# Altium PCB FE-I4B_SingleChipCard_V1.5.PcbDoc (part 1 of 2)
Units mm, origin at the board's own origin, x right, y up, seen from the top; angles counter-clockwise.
Board outline 100 x 100 mm, 5 copper layers (Top Layer, pad layer, GND, power, Bottom Layer); 136 components, 118 nets, 544 pads, 176 vias.
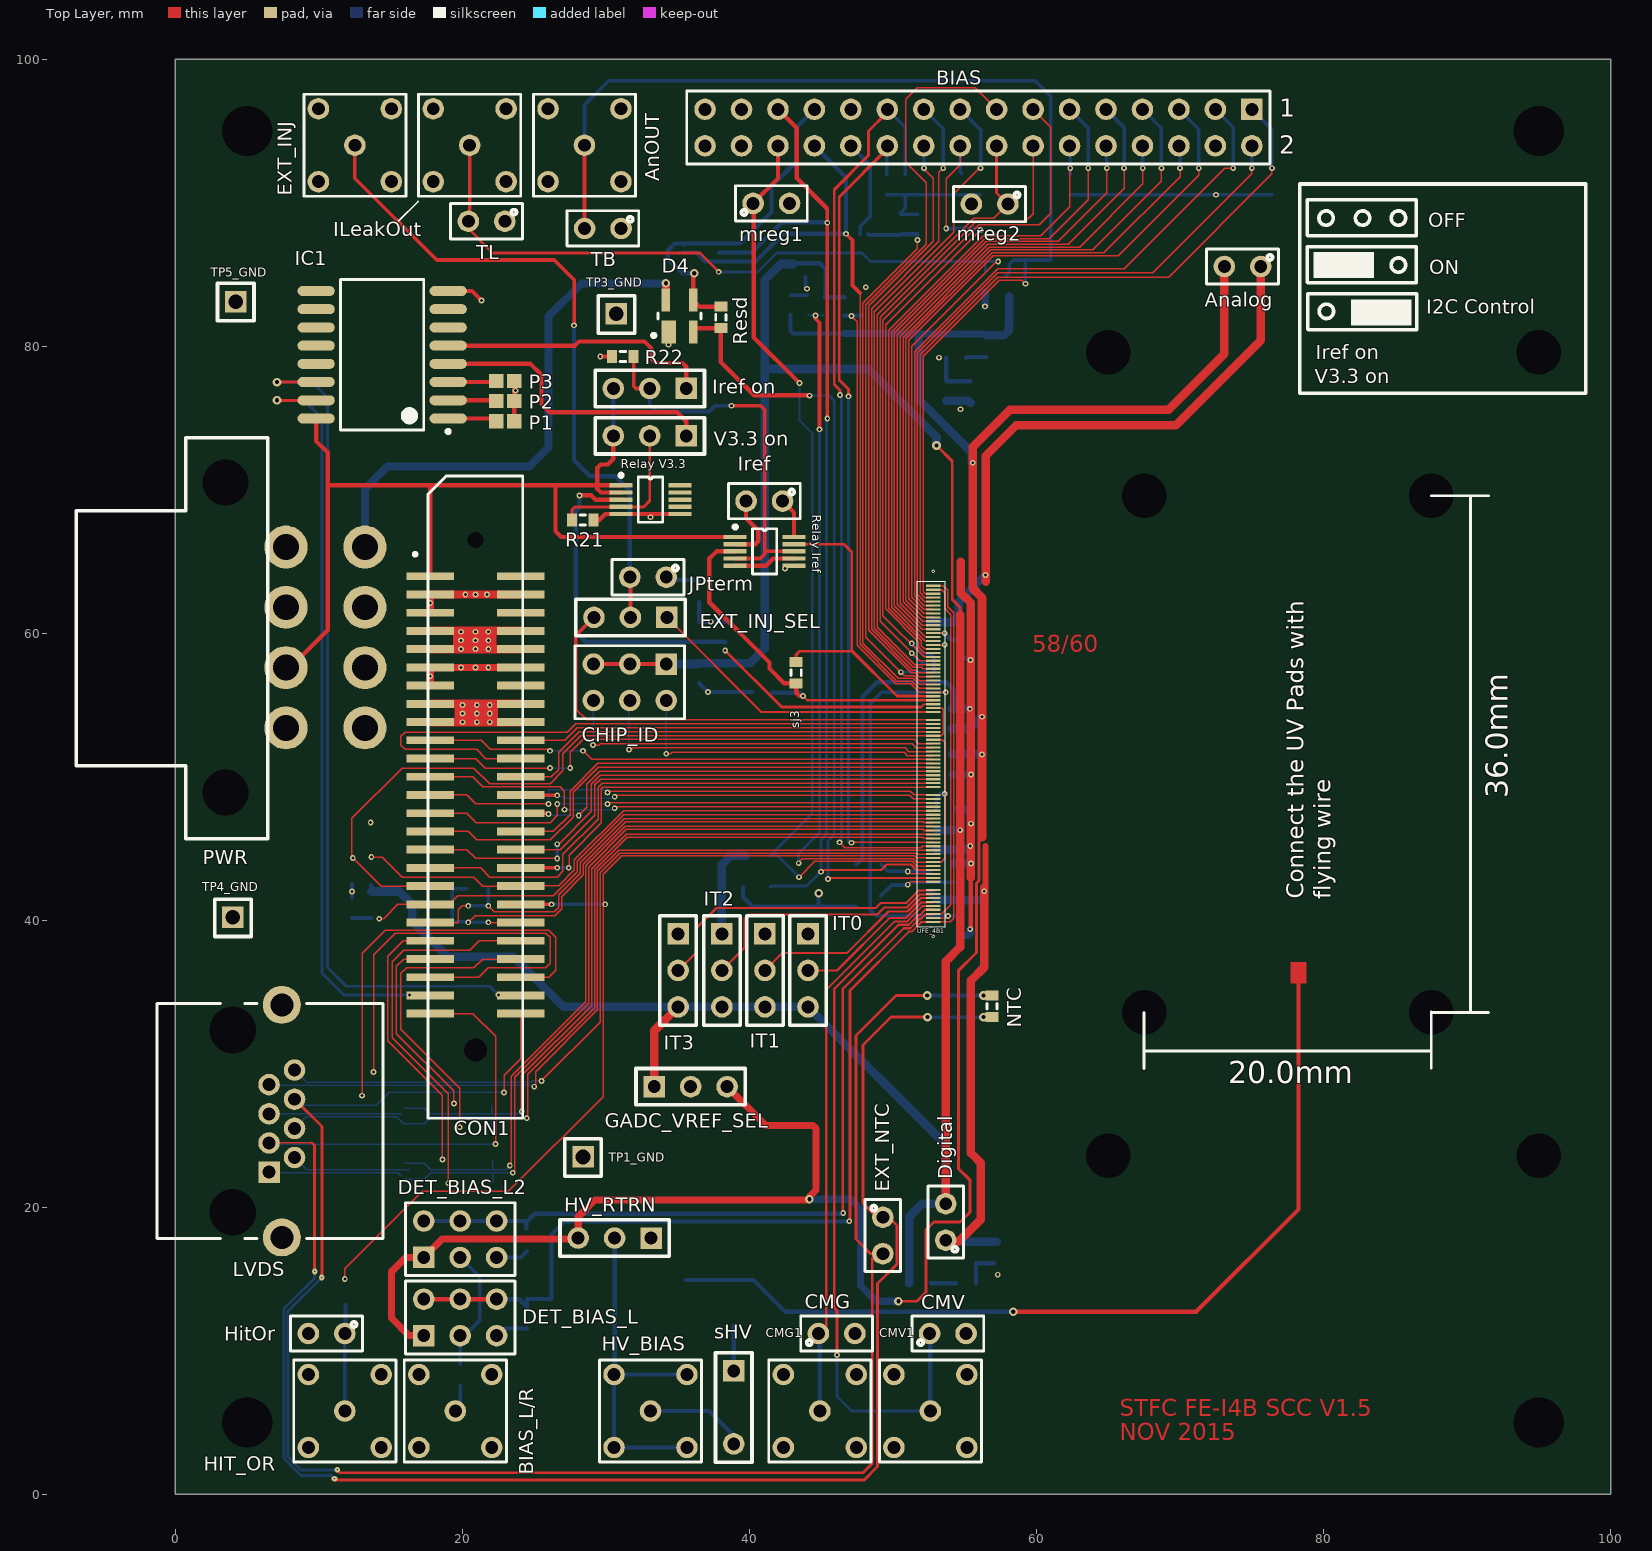
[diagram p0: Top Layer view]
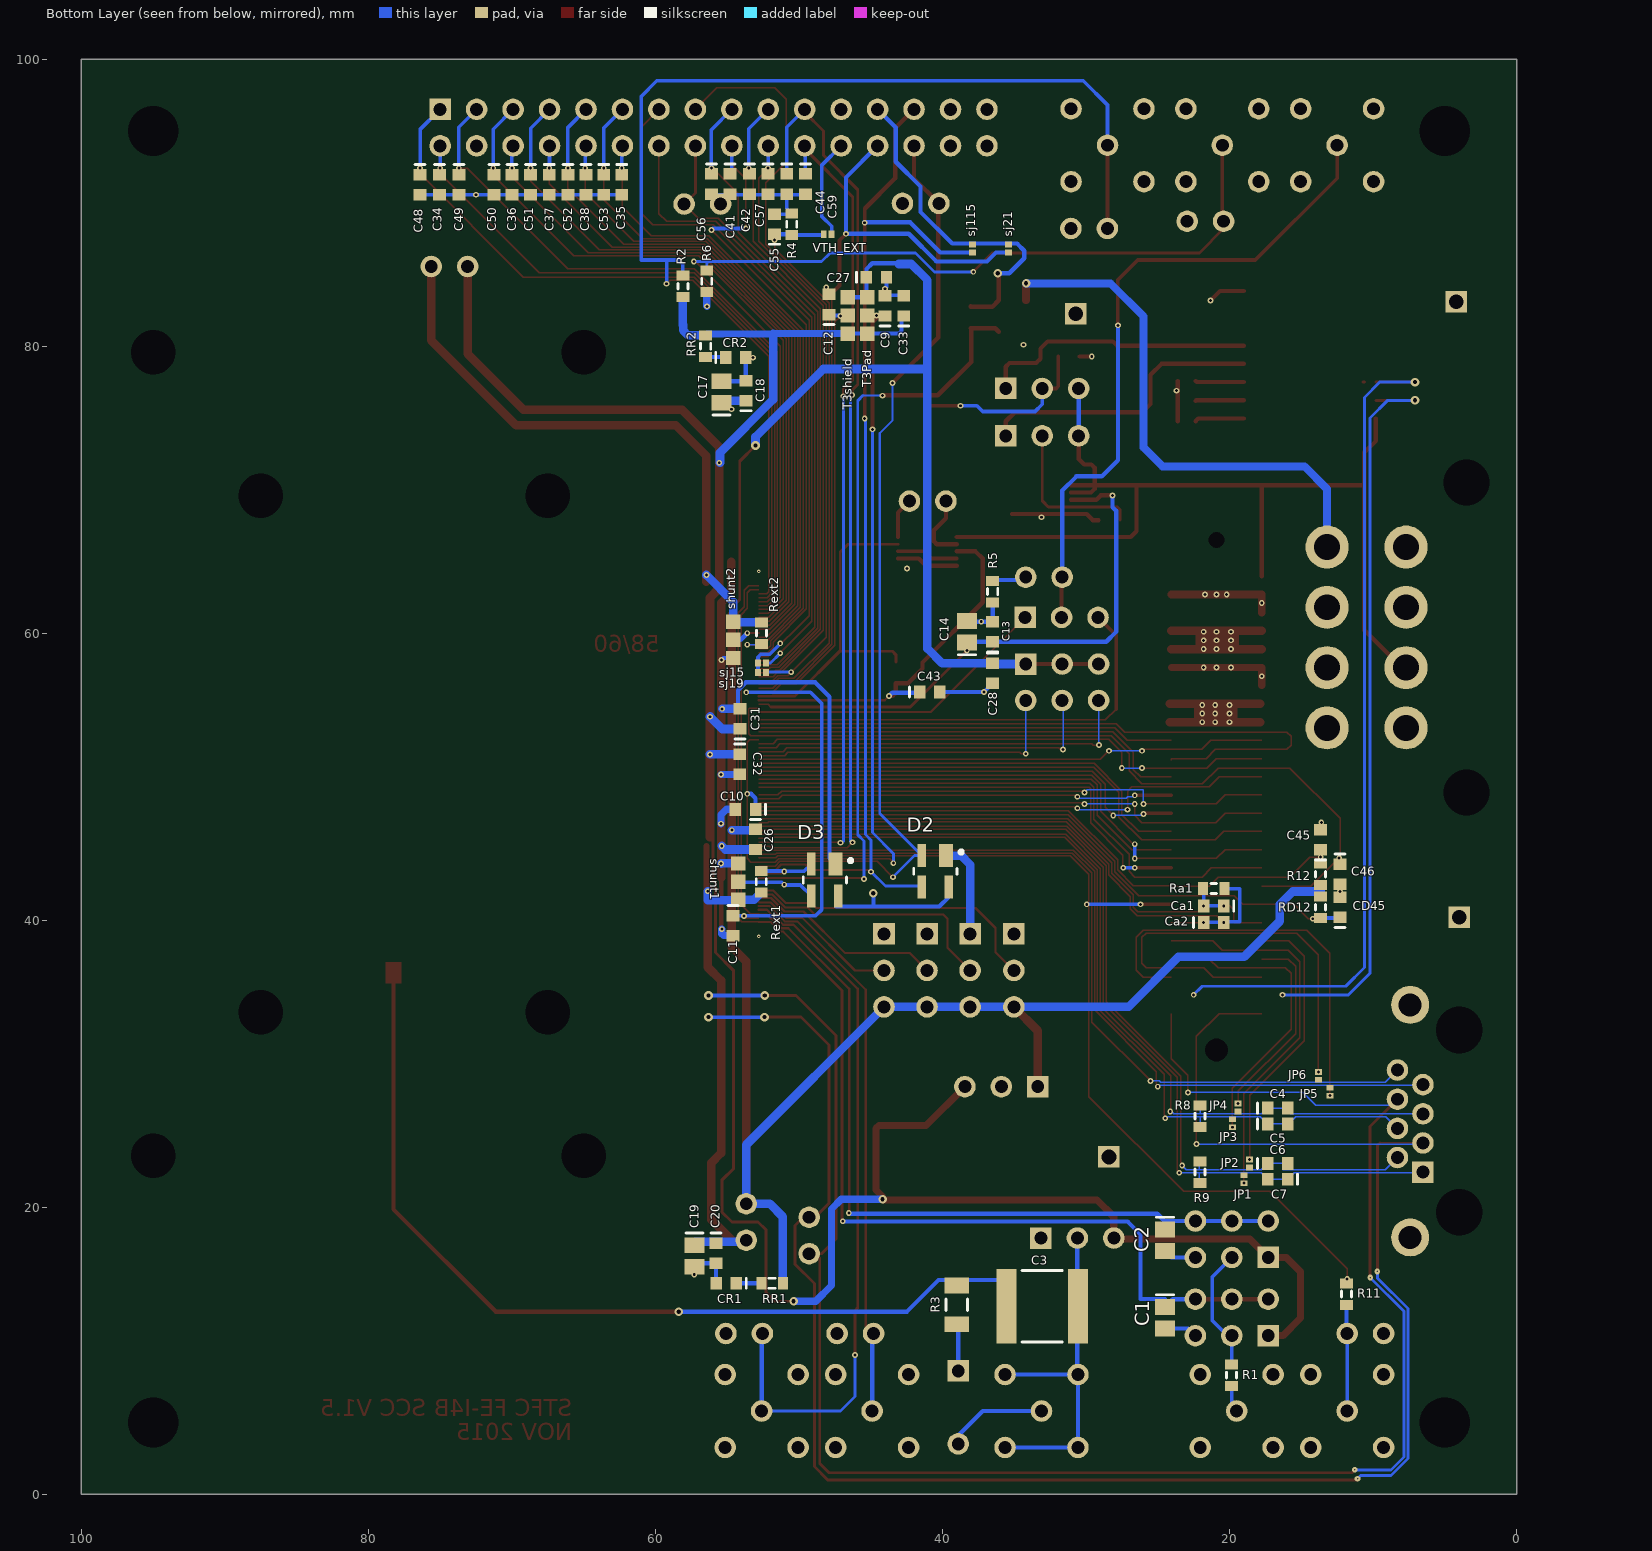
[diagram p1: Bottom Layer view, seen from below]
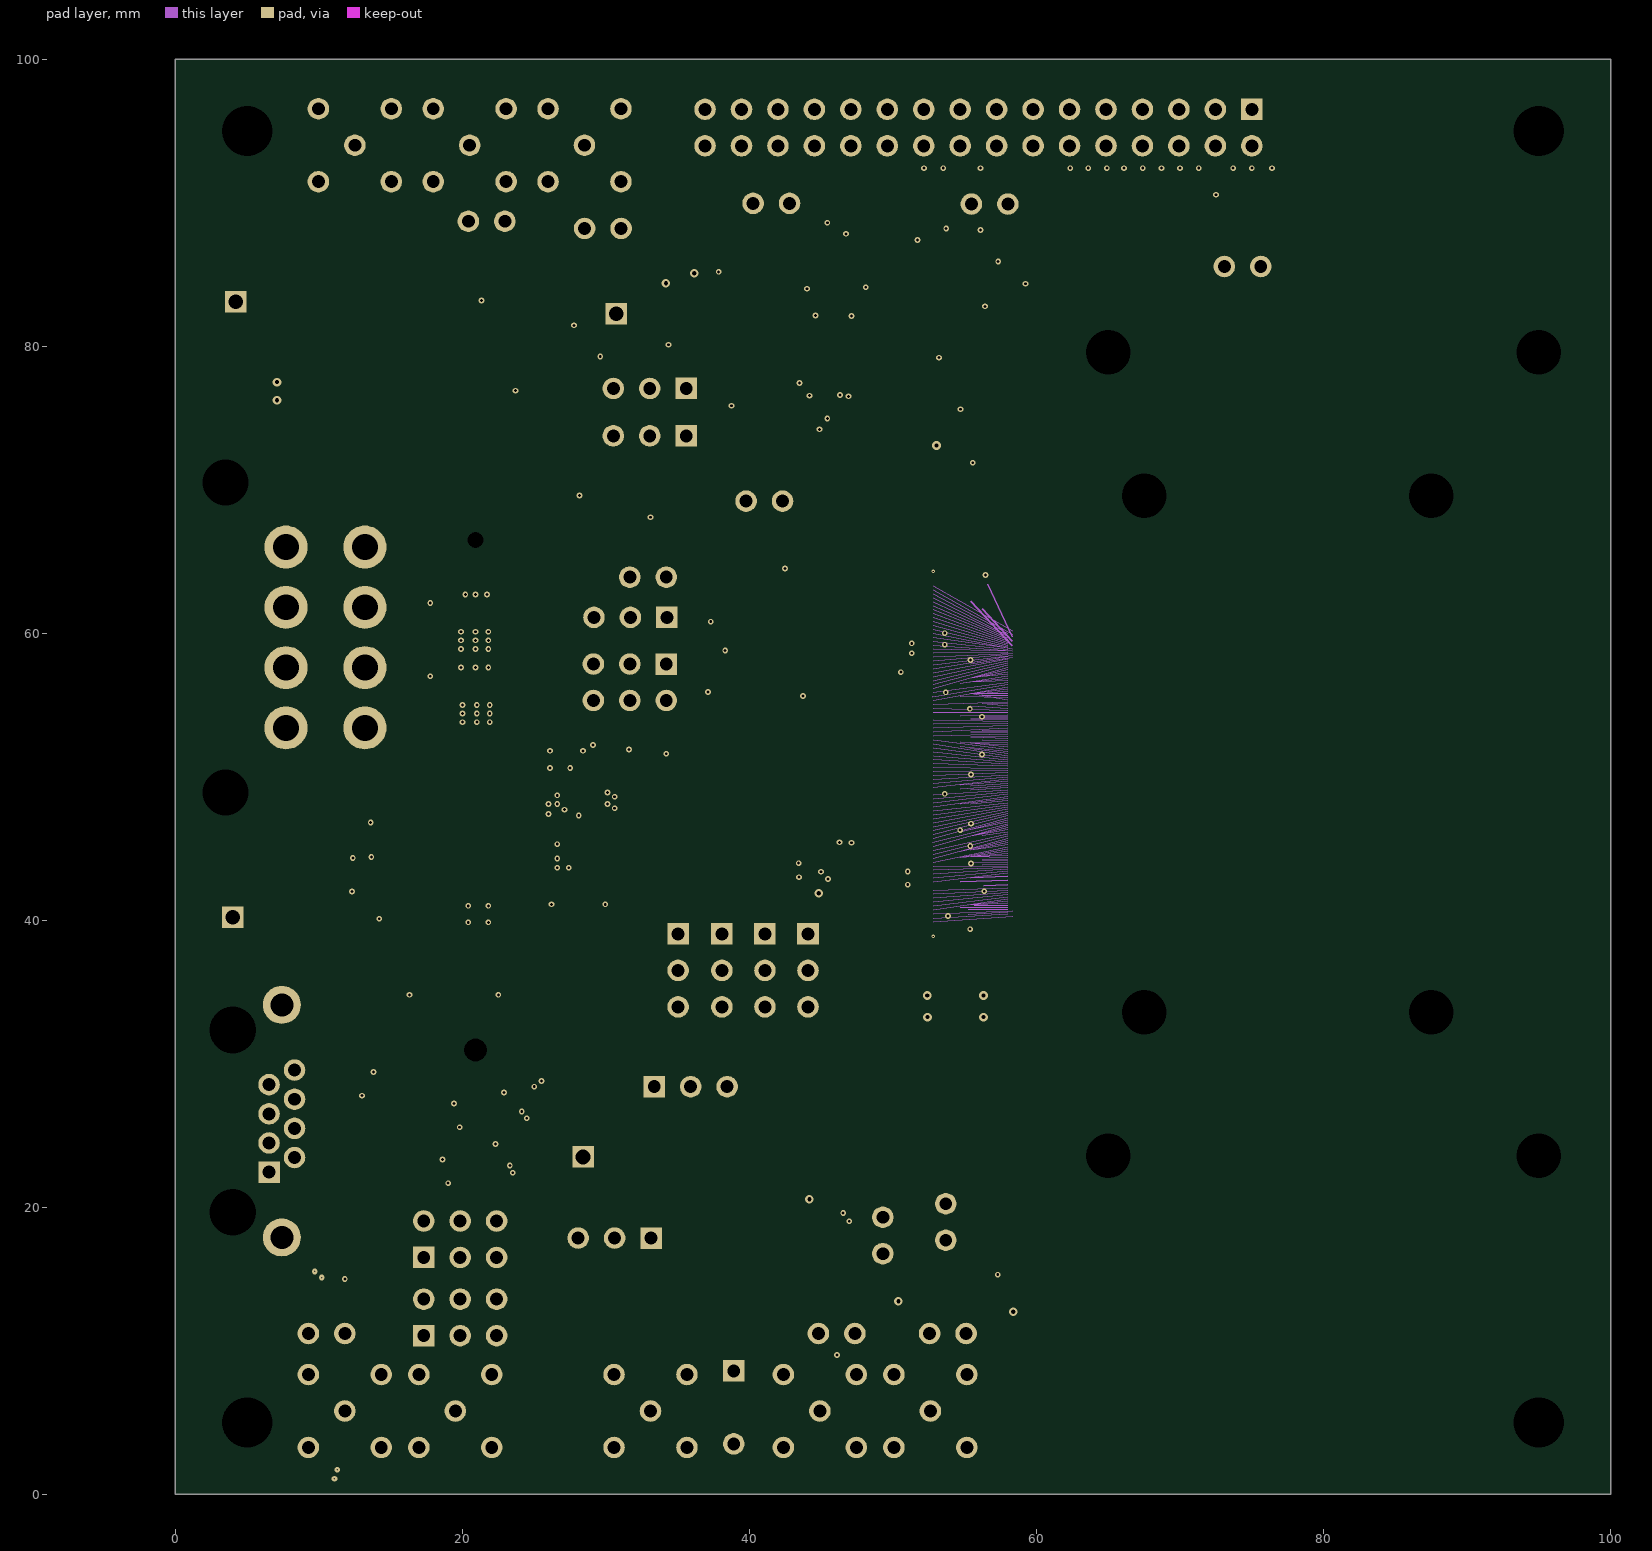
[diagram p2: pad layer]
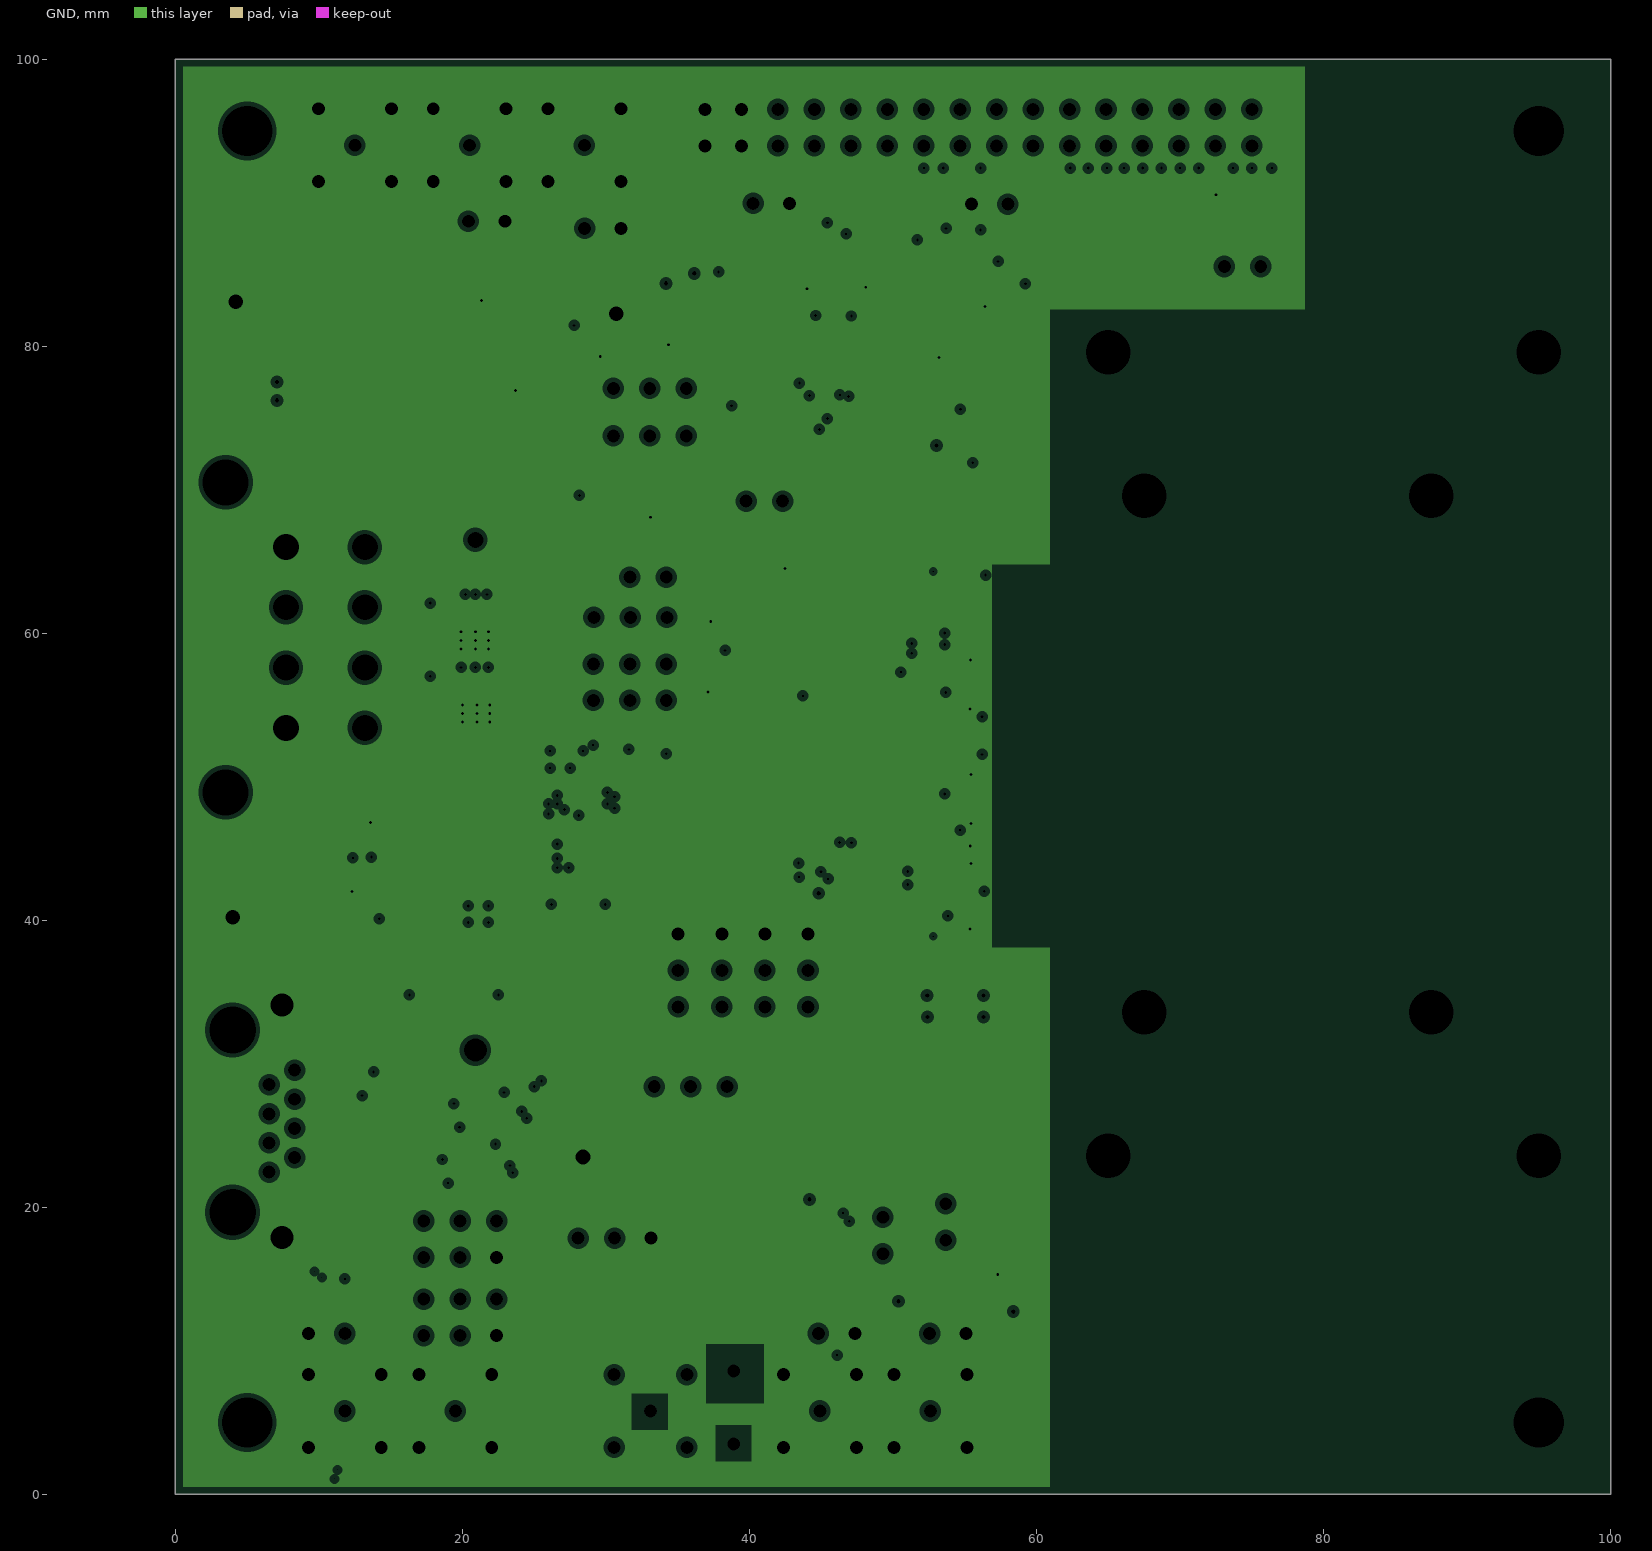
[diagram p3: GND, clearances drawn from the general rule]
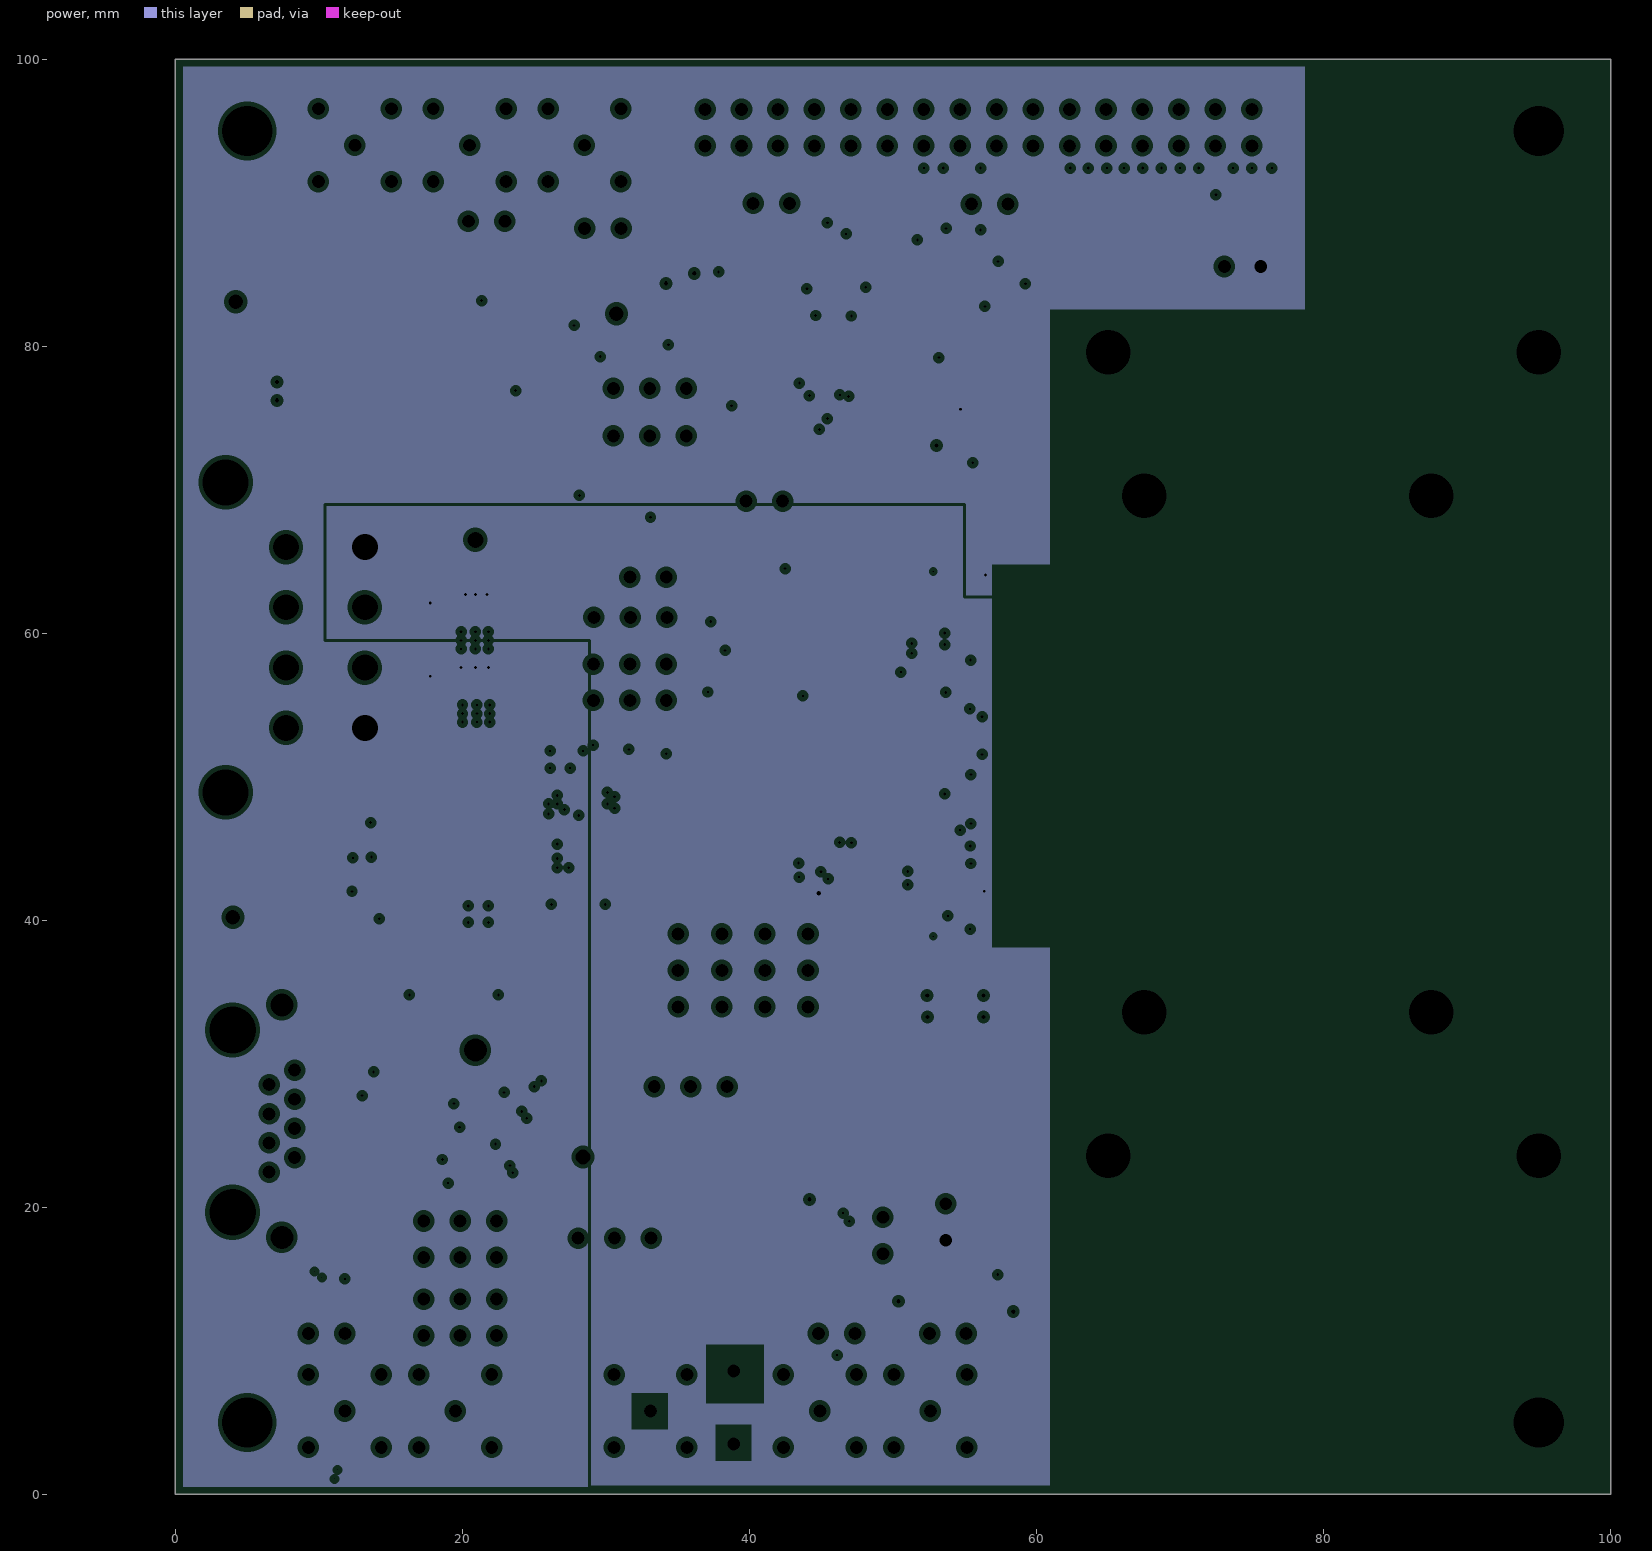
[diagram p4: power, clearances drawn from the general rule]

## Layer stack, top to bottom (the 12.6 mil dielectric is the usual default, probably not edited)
Top Solder: solder mask 0.0102, Solder Resist, Dk 3.5
Top Layer: signal copper 0.0356
Dielectric1: core 0.32, FR-4, Dk 4.8
pad layer: signal copper 0.0356
Dielectric2: prepreg 0.32, FR-4, Dk 4.8
GND: plane copper 0.0356, net GND
Dielectric3: core 0.32, FR-4, Dk 4.8
power: plane copper 0.0356, net (Multiple Nets)
Dielectric4: prepreg 0.32, FR-4, Dk 4.8
Bottom Layer: signal copper 0.0356
Bottom Solder: solder mask 0.0102, Solder Resist, Dk 3.5

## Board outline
0,0 0,100 100,100 100,0

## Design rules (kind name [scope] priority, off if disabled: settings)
Clearance "Clearance bot" [OnLayer('Bottom Layer')] p1: gap=0.09
Clearance "Clearance top" [OnLayer('Top Layer')] p2: gap=0.09
ComponentClearance [All] p1: gap=0.05 collisioncheckmode=3 verticalgap=0.254 showdistances=FALSE
FabricationTestPointUsage TestPointUsage [All] p1: valid=0 allowmultiple=FALSE
FabricationTestpoint Testpoint [All] p1: side=3 testpointundercomponent=TRUE minsize=1.016 maxsize=2.54 preferedsize=1.524 minholesize=0 maxholesize=1.016 preferedholesize=0.813 testpointgrid=0.025 allowsidetop=TRUE allowsidebottom=TRUE usegrid=TRUE gridtolerance=0
HoleSize [All] p1: absolutevalues=TRUE maxlimit=5 minlimit=0 maxpercent=80.000 minpercent=20.000
PlaneClearance [All] p1: clearance=0.3
PlaneConnect PlaneConnect_Thermal [(InComponent('U1') AND InNet('GNDA'))] p1: planeconnectstyle=Direct reliefexpansion=0.508 reliefentries=4 reliefconductorwidth=0.254 reliefairgap=0.254
PlaneConnect [NOT(InComponent('U1') AND InNet('GNDA'))] p2: planeconnectstyle=Direct reliefexpansion=0.508 reliefentries=4 reliefconductorwidth=0.254 reliefairgap=0.254
PolygonConnect PolygonConnect_Thermal [InNet('GNDA')] p1: connectstyle=Direct reliefconductorwidth=0.254 reliefentries=4 polygonreliefangle="90 Angle" airgapwidth=0.254
PolygonConnect [NOT(InComponent('U1') AND InNet('GNDA'))] p2: connectstyle=Relief reliefconductorwidth=0.254 reliefentries=4 polygonreliefangle="90 Angle" airgapwidth=0.254
RoutingLayers [OnLayer('pad layer')] p1: top layer_v5=TRUE mid layer 1_v5=TRUE bottom layer_v5=TRUE
RoutingVias [All] p1: holewidth=0.2 width=0.4 viastyle="Through Hole" minholewidth=0 minwidth=0.4 maxholewidth=4 maxwidth=5
ShortCircuit "ShortCircuit pad" [OnLayer('pad layer') vs OnLayer('pad layer')] p1: allowed=TRUE
ShortCircuit "ShortCircuit bot" [OnLayer('Bottom Layer')] p2: allowed=FALSE
ShortCircuit "ShortCircuit top" [OnLayer('Top Layer')] p3: allowed=FALSE
SilkToSolderMaskClearance SilkscreenOverComponentPads [IsPad] p1: minsilkscreentomaskgap=0.254 clearancetoexposedcopper=TRUE
SolderMaskExpansion [All] p1: expansion=0.102
UnConnectedPin [All] p1 off:
UnRoutedNet [NOT (OnLayer('padLayer'))] p1:
Width "Width pad" [All] p1: maxlimit=3 minlimit=0.01 preferedwidth=0.254 minimp=50.000000 maximp=50.000000 favimp=50.000000
Width "Width bot" [OnLayer('Bottom Layer')] p2: maxlimit=5 minlimit=0.125 preferedwidth=0.2
Width "Width top" [All] p3: maxlimit=4 minlimit=0.01 preferedwidth=0.25 minimp=50.000000 maximp=50.000000 favimp=50.000000
19 further rules are at their usual default settings.

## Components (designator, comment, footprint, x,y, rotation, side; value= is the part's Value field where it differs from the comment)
Analog "Jumper, 1x2" "CON 1x2 std" 75.625,85.55 r180 top
AnOUT "LEMO Connector" LEMO 28.5,94 r0 top
BIAS "Header 16X2" HDR2X16 75,96.5 r180 top locked
BIAS_L/R "LEMO Connector" LEMO 19.5,5.8 r0 top
C1 "X7R" C0805_imp_L 24.5,12.3 r270 bottom
C2 "X7R" C0805_imp_L 24.5,17.7 r270 bottom
C3 "X7R" C5750_met_L 33.05,13.1 r180 bottom
C4 "X7R" C0603_imp_L 16.65,26.9 r180 bottom
C5 "X7R" C0603_imp_L 16.65,25.8 r180 bottom
C6 "X7R" C0603_imp_L 16.65,23.05 r180 bottom
C7 "X7R" C0603_imp_L 16.65,21.95 r0 bottom
C9 "X7R" C0603_imp_L 44,82.8 r90 bottom
C10 "X7R" C0603_imp_L 53.725,47.725 r0 bottom
C11 "X7R" C0603_imp_L 54.6,39.625 r270 bottom
C12 "X7R" C0603_imp_L 47.9,82.9 r90 bottom
C13 "X7R" C0603_imp_L 36.5,60.1 r90 bottom
C14 "X7R" C0805_imp_L 38.3,60.1 r90 bottom
C17 "X7R" C0805_imp_L 55.4,76.8 r90 bottom
C18 "X7R" C0603_imp_L 53.7,76.9 r90 bottom
C19 "X7R" C0805_imp_L 57.275,16.6 r270 bottom
C20 "X7R" C0603_imp_L 55.775,16.8 r270 bottom
C26 "X7R" C0603_imp_L 53.025,45.625 r270 bottom
C27 "X7R" C0603_imp_L 44.6,84.8 r180 bottom
C28 "X7R" C0603_imp_L 36.5,57.2 r270 bottom
C31 "X7R" C0603_imp_L 54.1,54.025 r90 bottom
C32 "X7R" C0603_imp_L 54.125,50.875 r270 bottom
C33 "X7R" C0603_imp_L 42.7,82.8 r90 bottom
C34 "X7R" C0603_imp_L 75.05,91.25 r270 bottom
C35 "X7R" C0603_imp_L 62.35,91.25 r270 bottom
C36 "X7R" C0603_imp_L 70,91.25 r270 bottom
C37 "X7R" C0603_imp_L 67.4,91.25 r270 bottom
C38 "X7R" C0603_imp_L 64.85,91.25 r270 bottom
C41 "X7R" C0603_imp_L 54.8,91.3 r270 bottom
C42 "X7R" C0603_imp_L 53.45,91.3 r270 bottom
C43 "X7R" C0603_imp_L 40.9,55.9 r180 bottom
C44 "X7R" C0603_imp_L 50.85,91.3 r270 bottom
C45 "X7R" C0603_imp_L 13.65,45.6 r90 bottom
C46 "X7R" C0603_imp_L 12.3,43.2 r270 bottom
C48 "X7R" C0603_imp_L 76.4,91.25 r270 bottom
C49 "X7R" C0603_imp_L 73.7,91.25 r270 bottom
C50 "X7R" C0603_imp_L 71.25,91.25 r270 bottom
C51 "X7R" C0603_imp_L 68.7,91.25 r270 bottom
C52 "X7R" C0603_imp_L 66.1,91.25 r270 bottom
C53 "X7R" C0603_imp_L 63.6,91.25 r270 bottom
C55 "X7R" C0603_imp_L 51.7,88.5 r90 bottom
C56 "X7R" C0603_imp_L 56.1,91.3 r270 bottom
C57 "X7R" C0603_imp_L 52.15,91.3 r270 bottom
C59 "X7R" C0603_imp_L 49.55,91.3 r270 bottom
Ca1 "X7R" C0603_imp_L 21.1,41 r0 bottom
Ca2 "X7R" C0603_imp_L 21.1,39.85 r180 bottom
CD45 "X7R" C0603_imp_L 12.3,40.9 r90 bottom
CHIP_ID "Header 3X2" HDR2X3 34.2,57.85 r180 top
CMG "LEMO Connector" LEMO 44.9,5.8 r0 top
CMG1 "Jumper, 1x2" "CON 1x2 std" 44.8,11.2 r0 top
CMV "LEMO Connector" LEMO 52.6,5.8 r0 top
CMV1 "Jumper, 1x2" "CON 1x2 std" 52.55,11.2 r0 top
CON1 "KEL 8930E" "Kel_Connector 2x25; SMT" 17.6,64 r270 top locked
CR1 "X7R" C0603_imp_L 55.075,14.7 r0 bottom
CR2 "X7R" C0603_imp_L 54.4,79.2 r180 bottom
D2 "Molex 2X2" SOT143M 40.5,43.4 r270 bottom
D3 "Molex 2X2" SOT143M 48.2,42.8 r270 bottom
D4 "Molex 2X2" SOT143M 35.125,82.1 r90 top
DET_BIAS_L "Header 3X2" HDR2X3 17.3,11.05 r0 top
DET_BIAS_L2 "Header 3X2" HDR2X3 17.3,16.5 r0 top
Digital "Jumper, 1x2" "CON 1x2 std" 53.675,17.7 r90 top
EXT_INJ "LEMO Connector" LEMO 12.5,94 r0 top
EXT_INJ_SEL "Selector Jumper" "HDR 1x3" 31.7,61.1 r180 top
EXT_NTC "Jumper, 1x2" "CON 1x2 std" 49.288,19.3 r270 top
GADC_VREF_SEL "Selector Jumper" "HDR 1x3" 35.9,28.4 r0 top
HIT_OR "LEMO Connector" LEMO 11.8,5.8 r0 top
HitOr "Jumper, 1x2" "CON 1x2 std" 11.8,11.2 r180 top
HV_BIAS "LEMO Connector" LEMO 33.1,5.8 r0 top
HV_RTRN "Selector Jumper" "HDR 1x3" 30.6,17.85 r180 top
IC1 "i²C I/O" DW016_M 14.4,79.4 r180 top
ILeakOut "LEMO Connector" LEMO 20.5,94 r0 top
Iref "Jumper, 1x2" "CON 1x2 std" 42.3,69.2 r180 top
"Iref on" "Selector Jumper" "HDR 1x3" 33.05,77.05 r180 top
IT0 "Selector Jumper" "HDR 1x3" 44.075,36.5 r270 top
IT1 "Selector Jumper" "HDR 1x3" 41.075,36.5 r270 top
IT2 "Selector Jumper" "HDR 1x3" 38.075,36.5 r270 top
IT3 "Selector Jumper" "HDR 1x3" 35.025,36.5 r270 top
JP1 "Jumper, 1x2" "Lötjumper 1x2 - small" 19,21.95 r270 bottom
JP2 "Jumper, 1x2" "Lötjumper 1x2 - small" 18.6,23.05 r90 bottom
JP3 "Jumper, 1x2" "Lötjumper 1x2 - small" 19.8,25.85 r270 bottom
JP4 "Jumper, 1x2" "Lötjumper 1x2 - small" 19.4,26.95 r90 bottom
JP5 "Jumper, 1x2" "Lötjumper 1x2 - small" 13,28.05 r270 bottom
JP6 "Jumper, 1x2" "Lötjumper 1x2 - small" 13.8,29.15 r90 bottom
JPterm "Jumper, 1x2" "CON 1x2 std" 34.2,63.9 r180 top
LVDS "-" 44620-0002 -1.3,26 r270 top locked
mreg1 "Jumper, 1x2" "CON 1x2 std" 40.25,89.95 r0 top
mreg2 "Jumper, 1x2" "CON 1x2 std" 58,89.9 r180 top
NTC "R?" R0603_imp_L 56.9,34 r270 top
P1 "Jumper, Solderbridge 1x2" "Lötjumper 1x2" 22.986,74.773 r180 top
P2 "Jumper, Solderbridge 1x2" "Lötjumper 1x2" 22.986,76.173 r180 top
P3 "Jumper, Solderbridge 1x2" "Lötjumper 1x2" 22.986,77.573 r180 top
PWR "-" "MOLEX SD-5569" 7.7,66 r270 top locked
R1 "R?" R0603_imp_L 19.85,8.3 r90 bottom
R2 "R?" R0603_imp_L 58.075,84.175 r270 bottom
R3 "R?" R1206_imp_L 39,13.2 r90 bottom
R4 "R?" R0603_imp_L 50.5,88.5 r90 bottom
R5 "R?" R0603_imp_L 36.5,62.9 r90 bottom
R6 "R?" R0603_imp_L 56.425,84.525 r270 bottom
R8 "R?" R0603_imp_L 22.05,26.35 r90 bottom
R9 "R?" R0603_imp_L 22.05,22.45 r90 bottom
R11 "R?" R0603_imp_L 11.85,13.95 r90 bottom
R12 "R?" R0603_imp_L 13.65,43.2 r270 bottom
R21 "R?" R0603_imp_L 28.375,67.875 r180 top
R22 "R?" R0603_imp_L 31.175,79.275 r0 top
Ra1 "R?" R0603_imp_L 21.1,42.2 r0 bottom
RD12 "R?" R0603_imp_L 13.65,40.9 r90 bottom
"Relay Iref" "relay 4684EUB" UMAX10 41.05,65.7 r270 top
"Relay V3.3" "relay 4684EUB" UMAX10 33.1,69.3 r270 top
Resd "R?" R0603_imp_L 38,82 r90 top
Rext1 "R?" R0603_imp_L 52.625,42.675 r90 bottom
Rext2 "R?" R0603_imp_L 52.6,60 r270 bottom
RR1 "R?" R0603_imp_L 51.875,14.7 r180 bottom
RR2 "R?" R0603_imp_L 56.5,80 r90 bottom
shunt1 "Jumper, Solderbridge 1x3" solderjumper3 54.225,42.05 r90 bottom
shunt2 "Jumper, Solderbridge 1x3" solderjumper3 54.575,60.175 r270 bottom
sHV "Wire Bridge" "HDR 1;3" 38.9,6.05 r270 top
sj3 "R?" R0603_imp_L 43.25,57.25 r270 top
sj15 "Jumper, Solderbridge 1x2" "Lötjumper 1x2 - small" 52.578,57.912 r180 bottom
sj19 "Jumper, Solderbridge 1x2" "Lötjumper 1x2 - small" 52.578,57.25 r180 bottom
sj21 "Jumper, Solderbridge 1x2" "Lötjumper 1x2 - small" 35.4,86.8 r270 bottom
sj115 "Jumper, Solderbridge 1x2" "Lötjumper 1x2 - small" 37.9,86.8 r270 bottom
T3Pad "Jumper, Solderbridge 1x3" solderjumper3 45.25,81.5 r90 bottom
T3shield "Jumper, Solderbridge 1x3" solderjumper3 46.6,81.5 r90 bottom
TB "Jumper, 1x2" "CON 1x2 std" 31.05,88.2 r180 top
TL "Jumper, 1x2" "CON 1x2 std" 22.95,88.7 r180 top
TP1_GND "Test-Point" TEST_POINT 28.4,23.5 r270 top
TP3_GND "Test-Point" TEST_POINT 30.725,82.25 r270 top
TP4_GND "Test-Point" TEST_POINT 4,40.2 r270 top
TP5_GND "Test-Point" TEST_POINT 4.2,83.1 r270 top
UFE_4B1 "FE-I4B" "FE-I4B_PCB design" 52.8,63.3 r270 top
"V3.3 on" "Selector Jumper" "HDR 1x3" 33.05,73.75 r180 top
VTH_EXT "Jumper, Solderbridge 1x2" "Lötjumper 1x2 - small" 48,87.8 r180 bottom

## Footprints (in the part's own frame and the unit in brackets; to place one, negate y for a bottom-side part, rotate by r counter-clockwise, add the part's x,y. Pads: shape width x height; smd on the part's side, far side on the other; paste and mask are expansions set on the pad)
44620-0002 [mm]
  rect 1.5x1.5 hole 0.9: 1(3.556,7.82)
  round 1.5 hole 0.9: 2(2.54,9.598) 3(1.524,7.82) 4(0.508,9.598) 5(-0.508,7.82) 6(-1.524,9.598) 7(-2.54,7.82) 8(-3.556,9.598)
  round 2.65 hole 1.6: MH1(-8.103,8.709) MH2(8.103,8.709)
  round 2.95 hole 3.25 unplated: MH3(-6.35,5.28) MH4(6.35,5.28)
  silkscreen extent -8.19,0 8.19,15.75
C0603_imp_L [mm]
  rect 0.8x0.9 smd: 1(-0.7,0) 2(0.7,0)
  silkscreen extent -1.4,-0.35 -1.4,0.35, body extent -0.87,-0.48 0.87,0.48, height 0.85
C0805_imp_L [mm]
  rect 1.1x1.4 smd: 1(-0.75,0) 2(0.75,0)
  silkscreen extent -1.6,-0.6 -1.6,0.6, body extent -1.1,-0.72 1.1,0.72, height 1.1
C5750_met_L [mm]
  rect 1.4x5.2 smd: 1(-2.5,0) 2(2.5,0)
  silkscreen extent -1.4,-2.5 1.4,2.5, body extent -2.95,-2.63 2.95,2.63, height 1.35
"CON 1x2 std" [mm]
  round 1.5 hole 0.9: 1(0,0) 2(2.54,0)
  silkscreen extent -1.23,-1.23 3.78,1.23
DW016_M [mm] "16-Pin Plastic Small Outline Integrated Circuit 1.27 mm Pitch, IPC Low Density"
  oval 2.6x0.7 smd: 1(-4.6,4.445) 2(-4.6,3.175) 3(-4.6,1.905) 4(-4.6,0.635) 5(-4.6,-0.635) 6(-4.6,-1.905) 7(-4.6,-3.175) 8(-4.6,-4.445) 9(4.6,-4.445) 10(4.6,-3.175) 11(4.6,-1.905) 12(4.6,-0.635) 13(4.6,0.635) 14(4.6,1.905) 15(4.6,3.175) 16(4.6,4.445)
  silkscreen extent -4.72,-5.25 2.9,5.47, body extent -3.75,-5.25 3.75,5.25, height 2.65
"FE-I4B_PCB design" [mm] "bondpads FE-I4 on chip"
  rect 0.15x1 smd paste-1 mask+0: 1(0.55,0) 1b(0,0) 2(0.825,0) 2b(0.275,0) 3(1.1,0) 4(1.375,0) 5(1.65,0) 6(1.925,0) 6b(3.3,0) 7(2.2,0) 7b(4.125,0) 8(2.475,0) 8b(4.95,0) 9(2.75,0) 9b(5.5,0) 10(3.025,0) 11(3.575,0) 11b(22.875,0) 12(3.85,0) 12b(23.425,0) 13(4.4,0) 14(4.675,0) 15(5.225,0) 16(5.775,0) 17(6.05,0) 18(6.325,0) 19(6.6,0) 20(6.875,0) 21(7.15,0) 28(7.425,0) 29(7.7,0) 30(7.975,0) 37(8.25,0) 41(8.525,0) 42(8.8,0) 46(9.35,0) 47(9.625,0) 48(9.9,0) 49(10.175,0) 52(10.45,0) 59(10.725,0) 62(11,0) 63(11.275,0) 64(11.55,0) 65(11.825,0) 66(12.1,0) 67(12.375,0) 68(12.65,0) 69(12.925,0) 70(13.2,0) 71(13.475,0) 72(13.75,0) 73(14.025,0) 78(14.575,0) 79(14.85,0) 80(15.125,0) 81(15.4,0) 84(15.675,0) 85(15.95,0) 86(16.225,0) 87(16.5,0) 88(16.775,0) 89(17.05,0) 90(17.325,0) 91(17.6,0) 94(17.875,0) 95(18.15,0) 99(18.425,0) 100(18.7,0) 101(18.975,0) 105(19.25,0) 114(19.525,0) 115(19.8,0) 116(20.075,0) 117(20.35,0) 118(20.625,0) 122(21.2,0) 123(21.475,0) 124(21.75,0) 125(22.025,0) 126(22.3,0) 127(22.575,0) 134(23.15,0)
  silkscreen extent -0.3,-1.1 23.75,0.85
HDR2X3 [mm] "Connector; Header; 3x2 Position"
  rect 1.5x1.5 hole 0.9: 1(0,0)
  round 1.5 hole 0.9: 2(0,2.54) 3(2.54,0) 4(2.54,2.54) 5(5.08,0) 6(5.08,2.54)
  silkscreen extent -1.27,-1.27 6.35,3.81
HDR2X16 [mm] "Connector; Header; 16x2 Position"
  rect 1.5x1.5 hole 0.9: 1(0,0)
  round 1.5 hole 0.9: 2(0,2.54) 3(2.54,0) 4(2.54,2.54) 5(5.08,0) 6(5.08,2.54) 7(7.62,0) 8(7.62,2.54) 9(10.16,0) 10(10.16,2.54) 11(12.7,0) 12(12.7,2.54) 13(15.24,0) 14(15.24,2.54) 15(17.78,0) 16(17.78,2.54) 17(20.32,0) 18(20.32,2.54) 19(22.86,0) 20(22.86,2.54) 21(25.4,0) 22(25.4,2.54) 23(27.94,0) 24(27.94,2.54) 25(30.48,0) 26(30.48,2.54) 27(33.02,0) 28(33.02,2.54) 29(35.56,0) 30(35.56,2.54) 31(38.1,0) 32(38.1,2.54)
  silkscreen extent -1.27,-1.27 39.37,3.81
"HDR 1;3" [mm] "Steckjumper 2 pins"
  rect 1.5x1.5 hole 0.9: 1(-2.54,0)
  round 1.5 hole 0.9: 3(2.54,0)
  silkscreen extent -3.81,-1.27 3.81,1.27
"HDR 1x3" [mm]
  rect 1.5x1.5 hole 0.9: 1(-2.54,0)
  round 1.5 hole 0.9: 2(0,0) 3(2.54,0)
  silkscreen extent -3.81,-1.27 3.81,1.27
"Kel_Connector 2x25; SMT" [mm]
  rect 0.55x3.3 smd: 1(0.035,0.15) 2(0.035,6.45) 3(1.305,0.15) 4(1.305,6.45) 5(2.575,0.15) 6(2.575,6.45) 7(3.845,0.15) 8(3.845,6.45) 9(5.115,0.15) 10(5.115,6.45) 11(6.385,0.15) 12(6.385,6.45) 13(7.655,0.15) 14(7.655,6.45) 15(8.925,0.15) 16(8.925,6.45) 17(10.195,0.15) 18(10.195,6.45) 19(11.465,0.15) 20(11.465,6.45) 21(12.735,0.15) 22(12.735,6.45) 23(14.005,0.15) 24(14.005,6.45) 25(15.275,0.15) 26(15.275,6.45) 27(16.545,0.15) 28(16.545,6.45) 29(17.815,0.15) 30(17.815,6.45) 31(19.085,0.15) 32(19.085,6.45) 33(20.355,0.15) 34(20.355,6.45) 35(21.625,0.15) 36(21.625,6.45) 37(22.895,0.15) 38(22.895,6.45) 39(24.165,0.15) 40(24.165,6.45) 41(25.435,0.15) 42(25.435,6.45) 43(26.705,0.15) 44(26.705,6.45) 45(27.975,0.15) 46(27.975,6.45) 47(29.245,0.15) 48(29.245,6.45) 49(30.515,0.15) 50(30.515,6.45)
  round 1 hole 1.6: 81(33.06,3.3)
  round 1 hole 1.1: 82(-2.5,3.3)
  silkscreen extent -6.95,-1 37.8,6.6
LEMO [mm]
  round 1.5 hole 0.9: 1(0,0) 2(-2.54,-2.54) 2(-2.54,2.54) 2(2.54,-2.54) 2(2.54,2.54)
  silkscreen extent -3.56,-3.56 3.56,3.56
"Lötjumper 1x2" [mm] "Lötjumper, 2 Pins"
  rect 1x1 smd mask+0: 1(-0.625,0) 2(0.625,0)
"Lötjumper 1x2 - small" [mm]
  rect 0.4x0.5 smd mask+0: 1(-0.275,0) 2(0.275,0)
"MOLEX SD-5569" [mm]
  round 3 hole 1.8: 1(12.6,5.5) 2(12.6,0) 3(8.4,5.5) 4(8.4,0) 5(4.2,5.5) 6(4.2,0) 7(0,5.5) 8(0,0)
  round 0 hole 3.2 unplated: 9(-4.5,-4.2)
  round 0 hole 3.2: 10(17.1,-4.2)
  silkscreen extent -7.62,-14.6 20.32,-1.27
R0603_imp_L [mm]
  rect 0.7x0.9 smd: 1(-0.75,0) 2(0.75,0)
  silkscreen extent -0.2,-0.35 0.2,0.35, body extent -0.85,-0.48 0.85,0.48, height 0.6
R1206_imp_L [mm]
  rect 1.1x1.7 smd: 1(-1.35,0) 2(1.35,0)
  silkscreen extent -0.4,-0.75 0.4,0.75, body extent -1.68,-0.87 1.68,0.87, height 0.71
solderjumper3 [mm]
  rect 1x1 smd mask+0: 1(-0.625,0) 2(0.635,0) 3(1.905,0)
SOT143M [mm] "SOT143, 4-Leads, Body 2.9x1.3mm, Pitch 1.9mm, Lead Span 2.5mm, IPC Low Density"
  rect 1.6x1 smd: 1(-1.1,0.75)
  rect 1.6x0.6 smd: 2(-1.1,-0.95) 3(1.1,-0.95) 4(1.1,0.95)
  silkscreen extent -1.47,-1.5 0.2,1.92, body extent -0.7,-1.52 0.7,1.52, height 1.1
TEST_POINT [mm] "1pin_gnd"
  rect 1.5x1.5 hole 1.02: 1(0,0)
  silkscreen extent -1.27,-1.27 1.34,1.27
UMAX10 [mm] "Shrink Small Outline; 10 Leads; Body Width 3 mm; Pitch 0.5 mm"
  rect 0.3x1.6 smd: 1(-1,-2.05) 2(-0.5,-2.05) 3(0,-2.05) 4(0.5,-2.05) 5(1,-2.05) 6(1,2.05) 7(0.5,2.05) 8(0,2.05) 9(-0.5,2.05) 10(-1,2.05)
  silkscreen extent -1.82,-2.17 1.58,0.85

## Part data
Analog: library part "JUMPER 1X2S", "KEL  8930E-050-178MS-F  - 8930E 50 pin PCB SMD connector"
AnOUT BIAS_L/R CMG CMV EXT_INJ HIT_OR HV_BIAS ILeakOut: library part "LEMO coax", "LEMO - EPL.00.250.NTN - SOCKET, 00, RIGHT ANGLE, PCB, 50OHM"
BIAS: "Header, 16-Pin, Dual row"
C1 C2: library part C, "TDK - CGA4J3X7R1H105M125AE - CAPACITOR, 1UF, 0805, 50V, +/-20%"
C3: library part C, "AVX - 2225AC104KAZ1A - CAPACITOR CERAMIC 0.1UF 1000V, X7R, 10%, 2225"
C4 C5 C6 C7 Ca1 Ca2: library part C, "AVX - 06035C103JAT2A - CAP MLCC, 0.01UF, 50V, X7R, 5%, 0603"
C9 C10 C11 C12 C13 C18 C20 C26 C27 C28 C31 C32 C33 C34 C35 C36 C37 C38 C41 C42 C43 C44 C45 C46 C48 C49 C50 C51 C52 C53 C55 C56 C57 C59 CD45: library part C, "AVX - 0603YC104K4T4A - CAP, CERAMIC, 0.1UF, 16V, X7R, 0603"
C14 C17 C19: library part C, "AVX - 0805ZD226MAT2A - CAP MLCC, 22UF, 10V, X5R, 20%, 0805"
CHIP_ID DET_BIAS_L DET_BIAS_L2: "SAMTEC - TLW-103-05-G-D - HEADER, 2.54MM, DUAL, 6WAY"
CMG1 CMV1 Digital EXT_NTC HitOr Iref JP1 JP2 JP3 JP4 JP5 JP6 JPterm mreg1 mreg2 TB TL: library part "JUMPER 1X2S", "MOLEX - 22-03-2021 - HEADER, THT, VERTICAL, 2.54MM, 2WAY"
CON1: library part "CON KEL 8930E", "KEL  8930E-050-178MS-F  - 8930E 50 pin PCB SMD connector"
CR1 CR2: library part C, "MURATA - GRM188R71A225KE15D - CAP, CERAMIC, 2.2UF, 10V, X7R, 0603"
D2 D3 D4: library part CM1213A, "ESD Suppressors 2-ch. 8KV/1pF Ultra"
EXT_INJ_SEL GADC_VREF_SEL HV_RTRN "Iref on" IT0 IT1 IT2 IT3 "V3.3 on": library part "JUMPER 1X3S", "SAMTEC - TSW-103-07-F-S - HEADER, 2.54MM, THT VERT, 3WAY"
IC1: library part PCF8574, "NXP - PCF8574T/3,518 - IC, I/O EXPANDER, 8BIT, SOIC16"
LVDS: library part "RJ-45 Buchse", "Modular Jack, Right Angle RJ-45, Low Profile, Inverted, with all Panel Grounding Tabs, Shielded with RJ-11 Keepout Feature"
NTC: library part R, "Thermistor"
P1 P2 P3 sHV sj15 sj19 sj21 sj115 VTH_EXT: library part "JUMPER 1X2S"
PWR: library part "MOLEX SD-5569", "MOLEX 8 pin Power Connector, SD-5569"
R1: library part R, "VISHAY DRALORIC - CRCW0603100KFKEA - RESISTOR, 100K, 0.1W, 1%, 0603, SMD"
R2 R11 R12 R21 R22 RD12 sj3: library part R, "VISHAY DRALORIC - CRCW06031K00FKEA - RESISTOR, 1K, 0.1W, 1%, 0603, SMD"
R3: library part R, "BOURNS - CR0603-JW-103ELF - RESISTOR, 10K, 0.1W, 5%"
R4 R6: library part R, "VISHAY DRALORIC - CRCW060345K3FKEA - RESISTOR, 0603, 45K3, 1%"
R5: library part R, "VISHAY DALE - CRCW060350R0FKEA - RESISTOR, THICK FILM, 50R, 100MW, 1%"
R8 R9 Ra1: library part R, "PANASONIC - ERA3AEB101V - RESISTOR, 0603, 100R, 0.1%, 0.1W"
"Relay Iref" "Relay V3.3": ".5Ohm Dual SPDT Analog IC Switch"
Resd: library part R, "PANASONIC - ERJ3EKF2000V - RESISTOR, 0603, 200R 1%, 0.1W"
Rext1 Rext2: library part R, "SMD Chip Resistor"
RR1 RR2: library part R, "WELWYN - LRCS0603-1RFT5 - RESISTOR, 1R 1% 0603"
shunt1 shunt2 T3Pad T3shield: library part "JUMPER 1X3S"
TP1_GND TP3_GND TP4_GND TP5_GND: library part anschluss, "VERO - 20-2137 - TERMINAL, PCB, BLACK"
UFE_4B1: "IBL FE-I4B"

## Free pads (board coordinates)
  round 0 hole 3.5 unplated paste-0.5 mask+0.07: 0(5,5) 1(5,95) 2(95,95) 3(95,5)
  round 0 hole 3.1 unplated paste-0.5 mask+0.07: SMH1(67.5,33.575) SMH2(87.5,33.575) SMH3(87.5,69.575) SMH4(65,23.575) SMH4(65,79.575) SMH4(67.5,69.575) SMH4(95,23.575) SMH4(95,79.575)

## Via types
v1: diameter 0.4, hole 0.2, Top Layer to Bottom Layer, 157 vias
v2: diameter 0.6, hole 0.3, Top Layer to Bottom Layer, 13 vias
v3: diameter 0.4, hole 0.102, Top Layer to Bottom Layer, 4 vias
v4: diameter 0.25, hole 0, Top Layer to Bottom Layer, 2 vias

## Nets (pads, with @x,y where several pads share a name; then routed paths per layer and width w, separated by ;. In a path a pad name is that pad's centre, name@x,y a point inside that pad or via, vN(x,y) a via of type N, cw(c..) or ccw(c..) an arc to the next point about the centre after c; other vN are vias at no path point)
AMP2VBN: BIAS.8 C37.1 UFE_4B1.9 | length 45.4
  Top Layer w0.1: UFE_4B1.9@52.8,60.55 52.05,60.55 50.5,62.1 50.5,80.7 56.7,86.9 63,86.9 67.4,91.3 v1@67.4,92.3
  Bottom Layer w0.25: BIAS.8@67.38,93.96 67.38,92.42 v1(67.4,92.4)
AMP2VBP: BIAS.7 C51.1 UFE_4B1.8 | length 49.1
  Top Layer w0.1: UFE_4B1.8@52.8,60.825 52.075,60.825 50.7,62.2 50.7,80.6 56.8,86.7 63.9,86.7 68.7,91.5 v1(68.7,92.4)
  Bottom Layer w0.25: BIAS.7@67.38,96.5 68.7,95.18 v1(68.7,92.4)
AMP2VBPFF: BIAS.6 C36.1 UFE_4B1.7 | length 46.4
  Top Layer w0.1: UFE_4B1.7@52.8,61.1 52.1,61.1 50.9,62.3 50.9,80.5 56.9,86.5 64.7,86.5 70,91.8 v1@70,92.3
  Bottom Layer w0.25: v1(70,92.4) BIAS.6@70,93.88
AMP2VBPFOL: BIAS.9 C52.1 UFE_4B1.10 | length 48
  Top Layer w0.1: UFE_4B1.10@52.8,60.275 52.025,60.275 50.3,62 50.3,80.8 56.6,87.1 62.2,87.1 66.1,91 v1@66.1,92.3
  Bottom Layer w0.25: BIAS.9@64.84,96.5 66.1,95.24 v1(66.1,92.4)
ANOUT: AnOUT.1 R2.1 TB.2 UFE_4B1.1 | length 85.6
  Top Layer w0.1: UFE_4B1.1@52.8,62.75 52.25,62.75 52.1,62.9 52.1,79.3 57.4,84.6 58.975,84.6 v1(59.225,84.35)
  Top Layer w0.25: TB.2@28.5,88.2 AnOUT.1@28.5,94
  Bottom Layer w0.25: AnOUT.1@28.5,94 28.5,96.8 30.2,98.5 59.9,98.5 61,97.4 61,86 58.4,86 58.1,85.7 58.1,85.125 R2.1@57.9,84.925 ; v1@59.225,84.375 59.225,85.875
AUXCLKN: Ca1.1 Ca1.2 CON1.39 Ra1.2 UFE_4B1.86 | length 41
  Top Layer w0.1: CON1.39@17.75,39.835 19.71,39.835 19.71,40.71 20,41 v1(20.4,41) ; v1(21.8,41) 22.2,40.6 26.4,40.6 26.7,40.9 26.7,41.775 28.2,43.275 28.2,44 31.275,47.075 UFE_4B1.86@52.8,47.075
  Bottom Layer w0.25: v1(20.4,41) v1(21.8,41) Ra1.2@21.8,42.2
AUXCLKP: Ca2.1 Ca2.2 CON1.40 Ra1.1 UFE_4B1.87 | length 44.4
  Top Layer w0.1: v1(20.4,39.85) 20.875,40.325 26.425,40.325 26.9,40.8 26.9,41.65 28.4,43.15 28.4,43.9 31.375,46.875 52.1,46.875 52.175,46.8 UFE_4B1.87@52.8,46.8 ; v1@21.8,39.835 CON1.40@24.05,39.835 CON1.40@24.05,39.8
  Bottom Layer w0.25: Ra1.1@20.3,42.2 19.3,42.2 19.3,39.9 20.35,39.9 v1(20.4,39.85) v1(21.8,39.85)
BGVREFAN: BIAS.15 sj19.2 UFE_4B1.19 | length 54.8
  Top Layer w0.1: UFE_4B1.19@52.8,56.7 51.813,56.7 51.473,57.04 50.79,57.04 v1(50.546,57.284) 48.1,59.73 48.1,82.9 52.3,87.1 52.3,91.4 50.9,92.8 50.9,97.2 51.7,98 55.72,98 BIAS.15@57.22,96.5
  Bottom Layer w0.2: v1(50.546,57.284) 50.564,57.302 52.201,57.302 sj19.2@52.303,57.404
BGVREFDG: BIAS.27 D2.3 sj115.2 UFE_4B1.115 | length 75.4
  Top Layer w0.1: v1@44.975,43.4 v1@45.075,43.5
  Top Layer w0.15: v1@45.075,43.5 49.175,43.5 49.55,43.875 51.25,43.875 51.625,43.5 UFE_4B1.115@52.8,43.5
  Top Layer w0.25: v1(45.425,74.95) 45.425,89.6
  Top Layer w0.3: BIAS.27@41.98,96.5 43.3,95.18 43.3,91.7 45.388,89.613
  Bottom Layer w0.2: D2.3@41.45,42.3 41.525,42.375 43.975,42.375 v1(44.975,43.375) 45.1,43.375 44.975,43.5 44.975,45.575 45.375,45.975 v1@45.375,74.95
  Bottom Layer w0.3: sj115.2@37.9,86.525 40.15,86.525 42.25,88.625 44.875,88.625 v1@45.45,88.625
  other v1: 45.425,88.6
CAPMEASGND: CMG1.1 CMG.1 UFE_4B1.126 | length 39.6
  Top Layer w0.15: 45.345,35.145 50.12,39.92 51.002,39.92 52.082,41 UFE_4B1.126@52.8,41
  Top Layer w0.2: CMG1.1@44.8,11.2 45.345,11.745 45.345,35.145
  Top Layer w0.3: CMG1.1@44.8,11.2 CMG1.1@44.9,11.2
  Bottom Layer w0.3: CMG.1@44.9,5.8 CMG1.1@44.9,11.2
CAPMEASVIN: CMV1.1 CMV.1 UFE_4B1.127 | length 50
  Top Layer w0.15: 45.9,35.2 50.38,39.68 51.101,39.68 51.776,40.355 51.857,40.355 52.227,40.725 UFE_4B1.127@52.8,40.725
  Top Layer w0.2: 45.9,35.2 45.9,13 46.1,12.8 v1(46.1,9.7)
  Bottom Layer w0.2: v1(46.1,9.7) 46.1,6.8 47.1,5.8 CMV.1@52.6,5.8
  Bottom Layer w0.3: CMV.1@52.6,5.8 CMV1.1@52.6,11.2
CHIP_DET_BIAS: DET_BIAS_L2.3 DET_BIAS_L.3 R1.2 | length 8.7
  Bottom Layer w0.254: DET_BIAS_L2.3@19.84,16.5 21.2,15.14 21.2,12.1 20.14,11.04 19.85,11.04 R1.2@19.85,9.05
CMDALTPLS: CON1.19 UFE_4B1.66 | length 35.6
  Top Layer w0.1: CON1.19@17.75,52.535 21.3,52.535 21.935,51.9 v1@26.1,51.9 ; v1(28.4,51.8) 29,51.2 UFE_4B1.66@52.8,51.2
  Bottom Layer w0.1: v1(26.1,51.8) v1(28.4,51.8)
CMDCHIPID0: CHIP_ID.6 UFE_4B1.63 | length 27
  Top Layer w0.1: v1(29.1,52.2) 29.5,52.2 29.6,52.3 51.325,52.3 51.6,52.025 UFE_4B1.63@52.8,52.025
  Bottom Layer w0.1: v1(29.1,52.2) 29.1,55.29 CHIP_ID.6@29.12,55.31
CMDCHIPID1: CHIP_ID.4 UFE_4B1.64 | length 24.8
  Top Layer w0.1: v1(31.6,51.9) 31.8,51.9 31.9,52 50.85,52 51.1,51.75 UFE_4B1.64@52.8,51.75
  Bottom Layer w0.1: v1(31.6,51.9) 31.6,55.25 CHIP_ID.4@31.66,55.31
CMDCHIPID2: CHIP_ID.2 UFE_4B1.65 | length 22.4
  Top Layer w0.1: v1(34.2,51.6) 34.5,51.6 34.6,51.7 50.775,51.7 51,51.475 UFE_4B1.65@52.8,51.475
  Bottom Layer w0.1: v1(34.2,51.6) CHIP_ID.2@34.2,55.31
CMDDCIN: C4.1 C4.2 JP4.1 LVDS.5 R8.2 UFE_4B1.90 | length 62
  Top Layer w0.1: v1@24.1,26.7 24.1,29.15 29,34.05 29,43.6 31.4,46 UFE_4B1.90@52.775,46
  Bottom Layer w0.1: LVDS.5@6.52,26.508 C4.2@15.775,26.508 ; C4.2@15.95,26.9 C4.1@17.35,26.9 17.75,26.5 22,26.5 ; R8.2@22.05,27.1 22.05,26.55 22,26.5 ; v1@24.1,26.7 23.9,26.5 22,26.5
  other v1: 24.125,26.675
CMDDCIP: C5.1 C5.2 JP3.1 LVDS.4 R8.1 UFE_4B1.91 | length 61.5
  Top Layer w0.1: 24.55,26.45 24.55,29.25 29.2,33.9 29.2,43.5 31.475,45.775 52.075,45.775
  Top Layer w0.12: v1(24.475,26.2) 24.475,26.225 24.4,26.3 24.55,26.45 ; 52.075,45.775 52.15,45.7 UFE_4B1.91@52.8,45.7
  Bottom Layer w0.1: LVDS.4@8.298,25.492 9.106,26.3 15.4,26.3 C5.2@15.9,25.8 ; C5.2@15.95,25.8 C5.1@17.35,25.8 17.85,26.3 22,26.3 ; R8.1@22.05,25.6 22.05,26.25 22,26.3 ; v1(24.475,26.2) 24.475,26.225 24.4,26.3 22,26.3
CMDEXTTRIGGER: CON1.21 UFE_4B1.62 | length 37.1
  Top Layer w0.1: CON1.21@17.75,51.265 20.935,51.265 21.6,50.6 v1(26.1,50.6) ; v1@27.425,50.675 v1@27.5,50.75 ; v1(27.5,50.6) v1@27.5,50.75 ; 45.675,52.575 45.7,52.6 ; UFE_4B1.62@52.8,52.3 51.8,52.3 51.5,52.6 45.7,52.6 ; v1@27.5,50.75 27.5,51.7 28.4,52.6 45.7,52.6
  Bottom Layer w0.1: v1(26.1,50.6) v1(27.5,50.6)
DETBIASL: C1.1 DET_BIAS_L.2 DET_BIAS_L.4 DET_BIAS_L.6 UFE_4B1.1b UFE_4B1.12b | length 84.7
  Top Layer w0.1: UFE_4B1.12b@52.8,39.875 53.975,39.875 54.225,40.125 54.225,61.425 53.8,61.85 53.8,63 53.5,63.3 UFE_4B1.1b@52.8,63.3
  Top Layer w0.15: 47,35.1 51.1,39.2 51.3,39.2 51.975,39.875 UFE_4B1.12b@52.8,39.875
  Top Layer w0.2: v1@47,19 47,35.1
  Top Layer w0.3: DET_BIAS_L.2@17.3,13.59 DET_BIAS_L.4@19.84,13.59 DET_BIAS_L.6@22.38,13.59
  Bottom Layer w0.3: DET_BIAS_L.6@22.38,13.59 23.96,13.59 C1.1@24.5,13.05 24.5,13.6 26.2,13.6 26.2,18.1 27.1,19 v1@46.8,19
  other v1: 46.95,19.025
DETBIASL2: C2.1 DET_BIAS_L2.2 DET_BIAS_L2.4 DET_BIAS_L2.6 UFE_4B1.2b UFE_4B1.11b | length 78.3
  Top Layer w0.1: UFE_4B1.11b@52.8,40.45 53.4,40.45 54.025,41.075 54.025,61.3 53.6,61.725 53.6,62.825 53.4,63.025 UFE_4B1.2b@52.8,63.025
  Top Layer w0.15: 46.5,35.2 50.74,39.44 51.201,39.44 51.876,40.115 51.957,40.115 52.232,40.39 52.765,40.39 UFE_4B1.11b@52.8,40.425
  Top Layer w0.2: v1@46.5,19.54 46.5,35.2
  Bottom Layer w0.3: DET_BIAS_L2.2@17.3,19.04 DET_BIAS_L2.4@19.84,19.04 DET_BIAS_L2.6@22.38,19.04 24.445,19.04 ; C2.1@24.445,18.536 24.445,18.945 25.04,19.54 v1@46.5,19.54
  other v1: 46.525,19.59
DISVBN: BIAS.11 C53.1 UFE_4B1.12 | length 47.3
  Top Layer w0.1: UFE_4B1.12@52.8,59.45 52.25,59.45 49.9,61.8 49.9,81 56.4,87.5 60.9,87.5 63.6,90.2 v1@63.6,92.3
  Bottom Layer w0.25: BIAS.11@62.3,96.5 63.6,95.2 v1(63.6,92.4)
DOBOUTN: JP6.1 LVDS.8 UFE_4B1.100 | length 57.6
  Top Layer w0.1: v1(25.5,28.8) 29.6,32.9 29.6,43.3 30.97,44.67 51.565,44.67 51.635,44.6 UFE_4B1.100@52.8,44.6
  Bottom Layer w0.1: LVDS.8@8.298,29.556 9.154,28.7 24.8,28.7 24.9,28.8 v1(25.5,28.8)
DOBOUTP: JP5.1 LVDS.7 UFE_4B1.99 | length 59.4
  Top Layer w0.1: v1(25,28.4) 25.1,28.5 25.1,29.45 29.4,33.75 29.4,43.4 30.875,44.875 46.875,44.875 46.88,44.87 47.32,44.87 47.325,44.875 UFE_4B1.99@52.8,44.875
  Bottom Layer w0.1: LVDS.7@6.46,28.5 v1@25,28.5
EXTANINJECTIN: EXT_INJ_SEL.1 UFE_4B1.42 | length 21.3
  Top Layer w0.15: EXT_INJ_SEL.1@34.24,61.1 40.84,54.5 UFE_4B1.42@52.8,54.5
EXTDIGINJECTIN: EXT_INJ_SEL.3 UFE_4B1.46 | length 32.1
  Top Layer w0.1: 27.9,54.7 28.65,53.95 UFE_4B1.46@52.8,53.95
  Top Layer w0.25: 27.9,54.7 27.9,59.84 EXT_INJ_SEL.3@29.16,61.1
FDACVBN: BIAS.5 C50.1 UFE_4B1.6 | length 50.3
  Top Layer w0.1: UFE_4B1.6@52.8,61.375 52.125,61.375 51.1,62.4 51.1,80.4 56.5,85.8 57,86.3 65.7,86.3 71.3,91.9 v1(71.3,92.4)
  Bottom Layer w0.25: BIAS.5@69.92,96.5 71.3,95.12 v1(71.3,92.4)
GADCVREF: GADC_VREF_SEL.2
GND: "Relay Iref.6" "Relay V3.3.5" "Relay V3.3.6" AnOUT.2 BIAS.29 BIAS.30 BIAS.31 BIAS.32 BIAS_L/R.2 C1.2 C2.2 C9.2 C10.2 C11.2 C12.2 C13.2 C14.2 C17.2 C18.2 C19.2 C20.2 C26.2 C27.2 C28.2 C31.2 C32.2 C33.2 C34.2 C35.2 C36.2 C37.2 C38.2 C41.2 C42.2 C43.2 C44.2 C45.2 C46.2 C48.2 C49.2 C50.2 C51.2 C52.2 C53.2 C55.2 C56.2 C57.2 C59.2 CD45.2 CMG1.2 CMG.2 CMV1.2 CMV.2 CON1.7 CON1.8 CON1.9 CON1.10 CON1.15 CON1.16 CON1.17 CON1.18 CR1.2 CR2.2 D2.1 D3.1 D4.1 DET_BIAS_L2.5 DET_BIAS_L.5 EXT_INJ.2 HIT_OR.2 HitOr.2 HV_RTRN.1 IC1.8 ILeakOut.2 IT0.1 IT1.1 IT2.1 IT3.1 LVDS.MH1 LVDS.MH2 mreg1.2 mreg2.2 P1.1 P2.1 P3.1 PWR.2 PWR.8 R4.2 R5.1 R6.2 R21.1 R22.1 shunt1.3 shunt2.3 TB.1 TL.1 TP1_GND.1 TP3_GND.1 TP4_GND.1 TP5_GND.1 | length 145.7
  Top Layer w0.3: IC1.8@19,83.845 20.655,83.845 v1(21.325,83.175) ; P1.1@23.611,74.773 P3.1@23.611,77.573 ; R21.1@29.125,67.875 29.525,67.875 29.95,68.3 31.05,68.3 35.15,68.3 ; v1(29.6,79.275) R22.1@30.425,79.275 ; v1(55.375,39.375) 55.4,39.375 55.425,39.4 55.425,42.95
  Top Layer w0.6: CON1.9@17.75,58.885 CON1.10@24.05,58.885 ; CON1.7@17.75,60.155 CON1.8@24.05,60.155 ; CON1.17@17.85,53.8 CON1.18@24.15,53.8 ; CON1.15@17.85,55.07 CON1.16@24.15,55.07 ; 54.725,64.975 54.725,62.8 55.425,62.1 v1(55.425,50.15) v1(55.425,46.725) v1(55.425,43.95) 55.425,42.95
  Bottom Layer w0.25: C35.2@62.35,90.55 C48.2@76.4,90.55 ; C52.2@66.1,90.55 C52.2@66.14,90.51
  Bottom Layer w0.254: DET_BIAS_L.5@22.38,11.05 22.88,11.55 C1.2@24.5,11.55 ; DET_BIAS_L2.5@22.38,16.5 24.05,16.5 C2.2@24.5,16.95 ; C33.2@42.85,83.55 C9.2@44,83.55 ; v1@43.95,84.05 v1(44,84) ; C59.2@49.55,90.55 C44.2@50.85,90.55 ; R4.2@50.5,89.25 50.85,89.6 C44.2@50.85,90.55 ; R4.2@50.55,89.2 C55.2@51.7,89.2 ; C56.2@56.075,90.55 C44.2@50.85,90.55
  Bottom Layer w0.3: CD45.2@12.3,41.6 C46.2@12.3,42.5 ; C28.2@36.5,56.5 v1(37.1,55.9) C43.2@40.2,55.9 ; R5.1@36.5,62.15 C13.2@36.5,60.8 38.25,60.8 C14.2@38.3,60.85 ; C27.2@43.9,84.8 43.9,84.1 v1(44,84) ; D3.1@47.45,43.9 47.875,44.325 47.875,55.575 48.875,56.575 53.7,56.575 54.25,56.025 54.25,54.875 C31.2@54.1,54.725 ; CR2.2@53.7,79.2 C18.2@53.7,77.6 53.75,77.55 C17.2@55.4,77.55 ; shunt2.3@54.575,58.27 55.255,58.27 v1(55.4,58.125) ; v1(55.35,54.725) v1@55.425,54.8 ; v1(55.375,39.375) 55.4,39.375 v1@55.425,39.4 ; CR1.2@55.775,14.7 C20.2@55.775,16.1 C19.2@57.025,16.1
  Bottom Layer w0.5: C32.2@54.125,50.175 54.15,50.15 v1(55.425,50.15) ; C10.2@54.425,47.725 55.05,47.725 55.425,47.35 v1(55.425,46.725) ; C11.2@54.6,38.925 55.25,38.925 55.375,39.05 v1(55.375,39.375) ; v1(56.4,82.775) 56.425,82.8 R6.2@56.425,83.775
  Bottom Layer w0.6: IT2.1@38.075,39.04 38.075,43.875 38.7,44.5 D2.1@39.75,44.5 ; C26.2@53.025,44.925 55.125,44.925 v1@55.375,45.175 ; C31.2@54.1,54.725 v1(55.35,54.725) ; shunt1.3@54.225,43.955 55.42,43.955 v1(55.425,43.95)
  other v1: 57.3,15.3 12.3,42 55.38,45.17 13.6,46.8 20,53.8 21,53.8 21.9,53.8 20,54.4 21,54.4 21.9,54.4 20,55 21,55 21.9,55 19.9,58.9 20.9,58.9 21.8,58.9 19.9,59.5 20.9,59.5 21.8,59.5 19.9,60.1 20.9,60.1 21.8,60.1 37.3,60.8 42.475,64.5 33.1,68.075 23.7,76.9 53.2,79.2 34.35,80.1 48.1,84.1 72.5,90.55
HITOR: CON1.38 R11.2 UFE_4B1.101 | length 68.7
  Top Layer w0.1: v1(11.8,15) 11.8,15.7 17.2,21.1 23.2,21.1 29.8,27.7 29.8,43.2 31.08,44.48 51.486,44.48 51.606,44.36 52.765,44.36 UFE_4B1.101@52.8,44.325
  Top Layer w0.25: CON1.38@24.05,41.105 v1(26.2,41.105)
  Bottom Layer w0.25: v1(26.2,41.105) v1@30,41.105
  other v1: 29.95,41.105
HV_IN: R3.1 sHV.1 | length 3.2
  Bottom Layer w0.3: sHV.1@38.9,8.59 R3.1@38.9,11.75
HV_RET: C3.2 HV_BIAS.2 HV_RTRN.2 | length 24.8
  Bottom Layer w0.3: HV_BIAS.2@30.6,8.23 HV_RTRN.2@30.6,17.8 ; HV_BIAS.2@35.64,3.26 HV_BIAS.2@30.56,3.26 HV_BIAS.2@30.56,8.34 HV_BIAS.2@35.64,8.34
ILEAKOUT: ILeakOut.1 R6.1 TL.2 UFE_4B1.5 | length 73.3
  Top Layer w0.1: TL.2@20.41,88.19 TL.2@20.41,88.7 ; UFE_4B1.5@52.8,61.65 52.15,61.65 51.3,62.5 51.3,79.975 v1@57.263,85.938
  Top Layer w0.2: TL.2@20.41,88.19 22.1,86.5 36.55,86.5 v1@37.875,85.175 ; v1(37.85,85.175) v1@37.9,85.175
  Top Layer w0.254: TL.2@20.4,88.69 TL.2@20.41,88.7 20.5,88.79 ILeakOut.1@20.5,94
  Bottom Layer w0.2: v1(37.85,85.175) 40.55,85.175 41.875,86.5 47.825,86.5 48.425,85.9 56.3,85.9 ; R6.1@56.425,85.275 56.425,85.775 56.3,85.9 ; v1(57.325,85.9) 56.3,85.9
IOMXIN0: CON1.31 UFE_4B1.70 | length 39.6
  Top Layer w0.1: CON1.31@17.75,44.915 20.3,44.915 20.915,44.3 v1(26.6,44.3) ; v1@26.5,45.3 26.7,45.3 28.975,47.575 28.975,49.475 29.6,50.1 UFE_4B1.70@52.8,50.1
  Bottom Layer w0.1: v1@26.5,45.3 v1(26.6,45.3)
  Bottom Layer w0.25: v1(26.6,44.3) v1(26.6,45.3)
IOMXIN1: CON1.32 UFE_4B1.71 | length 32
  Top Layer w0.1: CON1.32@24.05,44.915 24.05,44.9 26.8,44.9 29.225,47.325 29.225,49.425 29.625,49.825 UFE_4B1.71@52.8,49.825
IOMXIN2: CON1.33 UFE_4B1.72 | length 40
  Top Layer w0.1: CON1.33@17.75,43.645 21.255,43.645 21.9,43 26.6,43 27,43.4 27,44.6 29.45,47.05 29.45,49.25 29.75,49.55 UFE_4B1.72@52.8,49.55
IOMXIN3: CON1.34 UFE_4B1.73 | length 32.9
  Top Layer w0.1: v1@27.425,43.825 27.425,44.525 29.675,46.775 29.675,49.175 29.775,49.275 UFE_4B1.73@52.8,49.275
  Top Layer w0.25: CON1.34@24.05,43.645 26.555,43.645 26.6,43.69 v1(26.6,43.65)
  Bottom Layer w0.25: v1(26.6,43.65) v1(27.4,43.65)
IOMXOUT0: CON1.25 UFE_4B1.78 | length 36.7
  Top Layer w0.1: CON1.25@17.75,48.725 20.3,48.725 20.925,48.1 v1@26.1,48.1 ; v1(30.1,48.9) 30.1,49 51.2,49 51.475,48.725 UFE_4B1.78@52.8,48.725
  Bottom Layer w0.1: v1@26.1,48.1 26,48.2 26,49.1 29.9,49.1 v1(30.1,48.9)
  other v1: 26,48.1
IOMXOUT1: CON1.26 UFE_4B1.79 | length 29.1
  Top Layer w0.1: CON1.26@24.05,48.7 CON1.26@24.05,48.725 ; v1@30.6,48.7 51.15,48.7 51.4,48.45 UFE_4B1.79@52.8,48.45
  Top Layer w0.25: CON1.26@24.05,48.7 v1(26.6,48.7)
  Bottom Layer w0.1: v1@26.6,48.6 27.1,48.6 27.2,48.5 30.6,48.5 v1(30.6,48.6) v1@30.6,48.7
IOMXOUT2: CON1.27 UFE_4B1.80 | length 36.4
  Top Layer w0.1: CON1.27@17.75,47.455 20.3,47.455 20.955,46.8 26.1,46.8 26.6,47.3 v1(26.6,48.1) ; v1(30.1,48.1) 30.1,48.175 UFE_4B1.80@52.8,48.175
  Bottom Layer w0.1: v1(26.6,48.1) v1(30.1,48.1)
IOMXSEL0: CON1.28 UFE_4B1.69 | length 31.1
  Top Layer w0.1: v1(26,47.4) v1@26,47.455 ; v1(28.1,47.3) 28.675,47.875 28.675,49.475 29.575,50.375 UFE_4B1.69@52.8,50.375
  Top Layer w0.25: CON1.28@24.05,47.455 v1@26,47.455
  Bottom Layer w0.1: v1(26,47.4) 26,47.3 v1(28.1,47.3)
IOMXSEL1: CON1.29 UFE_4B1.68 | length 38.4
  Top Layer w0.1: CON1.29@17.75,46.2 20.4,46.2 21,45.6 26.125,45.6 27.7,47.175 27.7,48.9 29.45,50.65 UFE_4B1.68@52.8,50.65
IOMXSEL2: CON1.30 UFE_4B1.67 | length 31.7
  Top Layer w0.1: CON1.30@24.05,46.185 26.335,46.185 27.5,47.35 27.5,49 29.425,50.925 UFE_4B1.67@52.8,50.925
